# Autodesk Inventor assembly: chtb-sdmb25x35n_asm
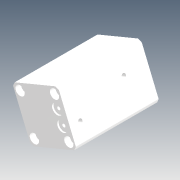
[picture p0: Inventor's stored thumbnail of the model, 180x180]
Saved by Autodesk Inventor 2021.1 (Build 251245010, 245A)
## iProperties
Company: Microsoft
Created: 2018-05
Part Number: chtb-sdmb25x35n_asm
Description: STEP AP214
Document SubType Name: Assembly
Designer: user
Title: chtb-sdmb25x35n_asm.STEP
Author: Windows
Revision Number: ÈÎºÎ
Sending System: SolidWorks 2015
Preprocessor: SwSTEP 2.0
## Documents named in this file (4)
- D:\Vault_2016\Projekty\Clamptek\Hydraulic\CHTB\CHTB-25\Inventor\chtb-sdmb25x35n\chtb-sdmb25x35n_asm.iam
- D:\Vault_2016\Projekty\Clamptek\Hydraulic\CHTB\CHTB-25\Inventor\chtb-sdmb25x35n\CHTB-25QG.ipt
- D:\Vault_2016\Projekty\Clamptek\Hydraulic\CHTB\CHTB-25\Inventor\chtb-sdmb25x35n\CHTB-SDMB25X35NBT.ipt
- D:\Vault_2016\Projekty\Clamptek\Hydraulic\CHTB\CHTB-25\Inventor\chtb-sdmb25x35n\CHTB-SDMB25X35NHSG.ipt
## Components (3 placed, 3 different names)
1. CHTB-25QG_1
2. CHTB-SDMB25X35NBT_2
3. CHTB-SDMB25X35NHSG_3
